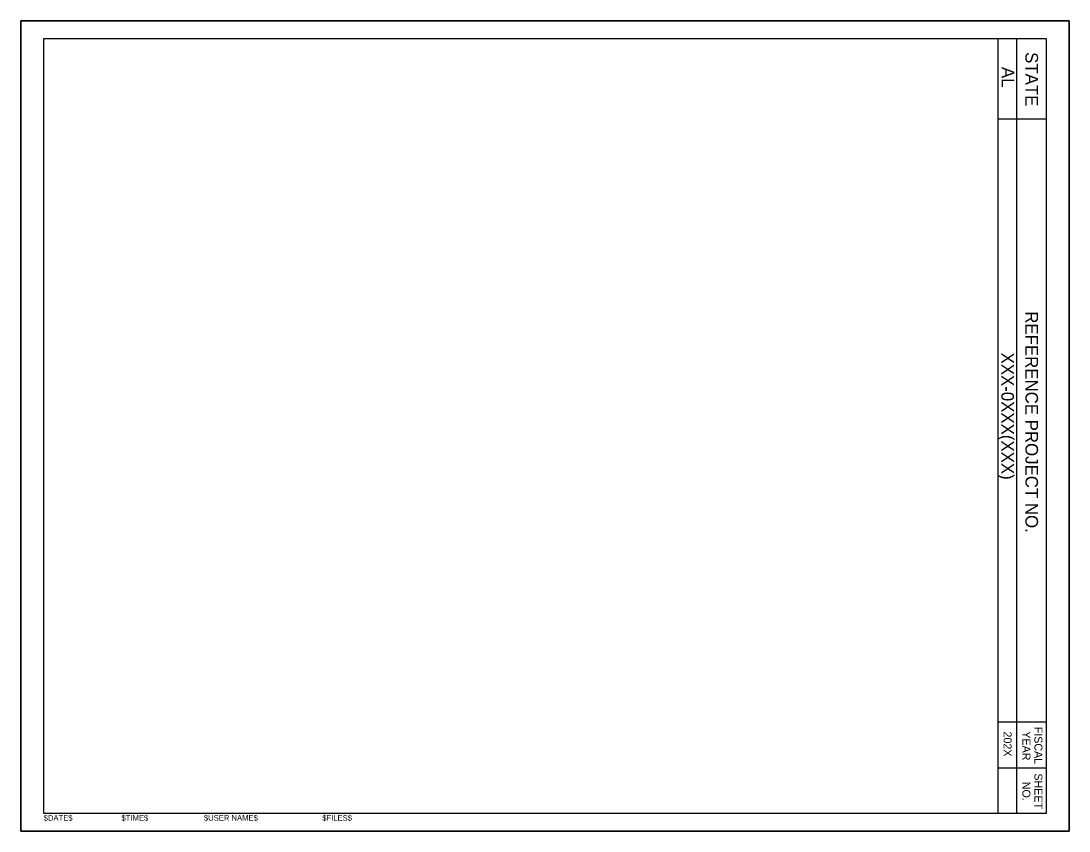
# Model space of a CAD drawing. Extents: x 0 to 0.917, y 0 to 0.708.
import ezdxf

# ---------------------------------------------------------------- set-up
doc = ezdxf.new("R2010")
doc.units = 0
for name, color, linetype in [('ANNO-TXT', 7, 'Continuous'), ('SHT-BDR', 7, 'Continuous'), ('SHT-FENCE', 7, 'Continuous')]:
    doc.layers.add(name, color=color, linetype=linetype)

msp = doc.modelspace()

# ---------------------------------------------------------------- linework, layer by layer
at = {"layer": 'SHT-BDR'}
for p, q in [((0.85476, 0.01536), (0.85476, 0.69298)), ((0.87076, 0.69298), (0.87076, 0.01536)), ((0.85476, 0.62283), (0.89679, 0.62283)), ((0.85476, 0.09536), (0.89679, 0.09536)), ((0.85476, 0.05536), (0.89679, 0.05536))]:
    msp.add_line(p, q, dxfattribs=at)
for points in [[(0, 0), (0.91666, 0), (0.91666, 0.70833), (0, 0.70833)], [(0.01986, 0.69298), (0.89679, 0.69298), (0.89679, 0.01536), (0.01986, 0.01536)]]:
    msp.add_lwpolyline(points, close=True, dxfattribs=at)
at = {"layer": 'SHT-FENCE'}
msp.add_lwpolyline([(0, 0.70833), (0.91666, 0.70833), (0.91666, 0), (0, 0)], close=True, dxfattribs=at)

# ---------------------------------------------------------------- texts
at = {"layer": 'ANNO-TXT'}
for s, height, p in [('STATE', 0.011, (0.87853, 0.68107)), ('AL', 0.011, (0.85775, 0.66812)), ('REFERENCE PROJECT NO.', 0.011, (0.87853, 0.45447)), ('XXX-0XXX(XXX)', 0.011, (0.85744, 0.41838)), ('202X', 0.007, (0.85944, 0.08703)), ('YEAR', 0.007, (0.87587, 0.08717)), ('FISCAL', 0.007, (0.88637, 0.09124)), ('SHEET', 0.007, (0.88637, 0.05039)), ('NO.', 0.007, (0.87587, 0.0431))]:
    msp.add_text(s, height=height, rotation=270, dxfattribs=at).set_placement(p)
for s, p in [('$DATE$', (0.01986, 0.00897)), ('$TIME$', (0.08792, 0.00897)), ('$USER NAME$', (0.16002, 0.00897)), ('$FILES$', (0.26349, 0.00897))]:
    msp.add_text(s, height=0.005, dxfattribs=at).set_placement(p)

doc.saveas('drawing.dxf')
